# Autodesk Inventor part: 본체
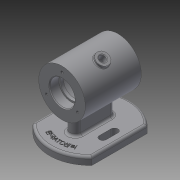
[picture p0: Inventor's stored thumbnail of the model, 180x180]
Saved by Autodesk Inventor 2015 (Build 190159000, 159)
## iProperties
Created: 2022-02
Part Number: 본체
Material: 일반
Document SubType Name: Modeling
Designer: pc-04
Density: 1 g/cm^3
Appearance: 기본값
Author: pc-04
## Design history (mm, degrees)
sketch "스케치1"
  geometry: C1 r 30 at (0, 0); 1 further point
  constraints: 1 centre point, 1 coincident
  dimensions: "d0" = 60 diameter of C1
extrude "돌출1" new body sketch "스케치1" distance "d1" = 72; taper "d2" = 0 deg
sketch "스케치2"
  geometry: L1 (72, -30)-(72, 30) reference; L2 (0, 0)-(72, 0); L3 (0, 0)-(12, 0); L4 (12, 0)-(12, 16); L5 (12, 16)-(0, 16); L6 (0, 16)-(0, 0); L7 (12, 0)-(16, 0); L8 (16, 0)-(16, 14); L9 (16, 14)-(12, 14); L10 (12, 14)-(12, 0); L11 (16, 0)-(56, 0); L12 (56, 0)-(56, 25); L13 (56, 25)-(16, 25); L14 (16, 25)-(16, 0); L15 (56, 0)-(60, 0); L16 (60, 0)-(60, 14); L17 (60, 14)-(56, 14); L18 (56, 14)-(56, 0); L19 (60, 0)-(72, 0); L20 (72, 0)-(72, 16); L21 (72, 16)-(60, 16); L22 (60, 16)-(60, 0); L23 (0, 30)-(0, -30) reference
  constraints: 42 end point, 10 parallel, 5 horizontal, 5 perpendicular, 2 point on line, 1 collinear, 1 midpoint
  dimensions: "d3" = 12 distance of L4.end L5.end; "d4" = 4 distance of L8.end L9.end; "d5" = 40 distance of L12.end L13.end; "d6" = 4 distance of L16.end L17.end; "d7" = 12 distance of L20.end L21.end; "d10" = 50 diameter of L13 L2; "d14" = 32 diameter of L5 L11; "d15" = 28 diameter of L9 L11; "d16" = 32 diameter of L21 L2
revolve "회전1" sketch "스케치2" stored, may be unused: angle "d13" = 90 deg
chamfer "모따기1" distance "d17" = 1; stored, may be unused: second distance "d18" = 2, angle "d19" = 45 deg
fillet "모깎기1" dims "d20" = 0.3
fillet "모깎기2" dims "d21" = 3
sketch "스케치3" dims "d22" = 46
  geometry: 5 further points
  constraints: 1 coincident, 1 vertical alignment, 6 other
  dimensions: "d25" = 360 deg dimension on point (0, 0) point (0, 23) (derived)
hole "구멍1" sketch "스케치3" at (0, 23), (-19.919, -11.5), (19.919, -11.5) diameter "d27" = 3.242; stored, may be unused: countersink angle "d31" = 90 deg, drill point angle "d33" = 118 deg; dims "d28" = 8, "d29" = 4, "d30" = 2, "d32" = 10
node "작업 평면1"
node "작업 평면2"
sketch "스케치4"
  geometry: L1 (30, 72)-(-30, 72) reference; L2 (0, 0)-(0, 72); L3 (-38, 0.504)-(-38, 71.496); L4 (38, 0.504)-(38, 71.496); A1 r 52 centre (0, 36) between (38, 71.496) and (-38, 71.496); A2 r 52 centre (0, 36) between (-38, 0.504) and (38, 0.504)
  constraints: 6 end point, 4 point on circle, 2 centre point, 2 midpoint, 2 parallel
  dimensions: "d38" = 52 radius of A2; "d39" = 52 radius of A1; "d40" = 76 diameter of L4 L2; "d41" = 76 distance between parallel lines of L4 L3
extrude "돌출2" join sketch "스케치4" distance "d42" = 10; taper "d43" = 0 deg
sketch "스케치5"
  geometry: L1 (38, 71.496)-(38, 0.504) reference; L2 (38, 36)-(-38, 36); L3 (-38, 0.504)-(-38, 71.496) reference; L4 (0, -16)-(0, 88); L5 (24, 36)-(-24, 36); L6 (-28.5, 28.5)-(-28.5, 43.5); L7 (-19.5, 28.5)-(-19.5, 31.093); L8 (-19.5, 31.093)-(-19.5, 43.5); L9 (19.5, 28.5)-(19.5, 43.5); L10 (28.5, 28.5)-(28.5, 43.5); A1 r 4.5 centre (-24, 28.5) between (-28.5, 28.5) and (-19.5, 28.5); A2 r 4.5 centre (-24, 43.5) between (-19.5, 43.5) and (-28.5, 43.5); A3 r 4.5 centre (24, 43.5) between (28.5, 43.5) and (19.5, 43.5); A4 r 4.5 centre (24, 28.5) between (19.5, 28.5) and (28.5, 28.5); A5 r 52 centre (0, 36) between (-38, 0.504) and (38, 0.504) reference; A6 r 52 centre (0, 36) between (38, 71.496) and (-38, 71.496) reference; 4 further points
  constraints: 16 end point, 10 point on circle, 7 tangent, 5 midpoint, 4 centre point, 3 horizontal alignment, 2 vertical alignment, 1 coincident, 1 horizontal, 1 point on line, 1 vertical
  dimensions: "d44" = 9 diameter of A1; "d45" = 9 diameter of A2; "d46" = 9 diameter of A3; "d47" = 9 diameter of A4; "d48" = 48 distance of A3.centre A2.centre; "d49" = 15 distance of A2.centre A1.centre; "d50" = 9.5 distance between parallel lines of L1 L10; "d51" = 14 distance from line of L5.start L1; "d52" = 7.5 distance from line of L10.end L2; "d53" = 4.90719 distance from line of L7.end L2
extrude "돌출3" cut sketch "스케치5" distance "d54" = 10; taper "d55" = 0 deg
sketch "스케치6"
  geometry: L1 (38, 71.496)-(38, 0.504) reference; L2 (-38, 0.504)-(-38, 71.496) reference; L3 (0, 17)-(0, 55); L4 (0, -16)-(0, 88); L5 (-7, 17)-(-7, 55); L6 (7, 17)-(7, 55); A1 r 52 centre (0, 36) between (-38, 0.504) and (38, 0.504) reference; A2 r 52 centre (0, 36) between (38, 71.496) and (-38, 71.496) reference; A3 r 7 centre (0, 17) between (-7, 17) and (7, 17); A4 r 7 centre (0, 55) between (7, 55) and (-7, 55); 2 further points
  constraints: 8 end point, 6 point on circle, 4 tangent, 2 centre point, 2 midpoint, 1 vertical, 1 vertical alignment
  dimensions: "d56" = 14 diameter of A3; "d57" = 14 diameter of A4; "d58" = 38 distance of L3.end L3.start
extrude "돌출4" join sketch "스케치6" stored distance "d59" = 10; taper "d60" = 0 deg
sketch "스케치7"
  geometry: L1 (0, -16)-(0, 88); C1 r 42.5 at (0, 36); A1 r 52 centre (0, 36) between (-38, 0.504) and (38, 0.504) reference; A2 r 52 centre (0, 36) between (38, 71.496) and (-38, 71.496) reference; 1 further point
  constraints: 2 end point, 2 point on circle, 1 centre point, 1 coincident, 1 other
  dimensions: "d61" = 85 diameter of C1
feature "엠보싱1" sketch "스케치7" dims "d3" = 12, "d4" = 4, "d5" = 40, "d6" = 4, "d7" = 12, "d10" = 50, "d14" = 32, "d15" = 28, "d16" = 32, "d62" = 0.5, "d63" = 0
fillet "모깎기3" dims "d64" = 3
fillet "모깎기4" dims "d65" = 3
fillet "모깎기5" dims "d66" = 3
sketch "스케치8"
  geometry: L1 (0, 0)-(0, 30); L2 (0, 0)-(25.981, 15); A1 r 30 centre (0, 0) between (0, 30) and (25.981, 15) reference; 1 further point
  constraints: 4 end point, 2 point on circle, 1 vertical
  dimensions: "d68" = 60 deg angle of L1 L2
node "작업 평면4"
node "작업 평면5"
sketch "스케치10"
  geometry: 1 further point
node "작업 평면6"
sketch "스케치11"
  geometry: L1 (30, 0)-(-30, 0) reference; L2 (-30, -72)-(30, -72) reference; L3 (0, 0)-(0, -72); C1 r 8 at (0, -36)
  constraints: 2 end point, 2 midpoint, 1 centre point
  dimensions: "d73" = 16 diameter of C1
extrude "돌출5" join sketch "스케치11" stored distance "d74" = 10; taper "d75" = 0 deg
sketch "스케치12"
  geometry: C1 r 8 at (0, 0) reference; C2 r 4 at (0, 0); 1 further point
  constraints: 1 centre point, 1 coincident
  dimensions: "d76" = 8 diameter of C2
extrude "돌출6" cut sketch "스케치12" stored distance "d77" = 10; taper "d78" = 0 deg
fillet "모깎기6" dims "d79" = 1
node "솔리드1"
mirror "대칭1"
other parameters: "d34" = -62, "d35" = 104, "d69" = 90 deg, "d72" = 33
